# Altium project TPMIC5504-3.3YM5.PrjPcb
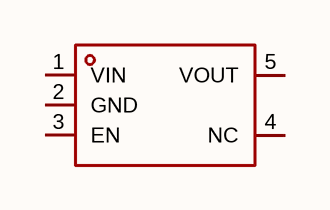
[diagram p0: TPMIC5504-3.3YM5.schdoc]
1 sheet, 1 parts. Net scope: global (net labels, ports and power ports of the same name join across sheets).

## Sheet TPMIC5504-3.3YM5.schdoc
size 127 x 101 mm

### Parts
U?  tpmic5504-3.3ym5  [SOT-23-5_L2.9-W1.6-P0.95-LS2.8-BR]  (value not drawn)

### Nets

Not connected (* = marked no-connect by the designer): U? 1(VIN) 2(GND) 3(EN) 4(NC) 5(VOUT)

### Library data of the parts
U? = tpmic5504-3.3ym5: 输出极性:正极;工作电压:5.5V;输出电压:3.3V;输出电流:300mA;电源纹波抑制比(PSRR):80dB@(100Hz);输出类型:固定;; Manufacturer: TECH PUBLIC(台舟); AddInBom: yes; ModelId: 7ba65df16e7b4570af156e925f9c37fe; ModelTransform: 114.173,114.173,0,90,0,0,0,0,0; Output Configuration: 正极; Voltage - Supply: 5.5V; Output Voltage: 3.3V; Output Current: 300mA; Voltage Dropout: 220mV@(300mA); standby current: 15uA; Output Type: 固定; Number of Outputs: 1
